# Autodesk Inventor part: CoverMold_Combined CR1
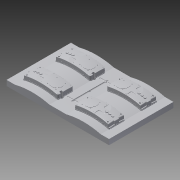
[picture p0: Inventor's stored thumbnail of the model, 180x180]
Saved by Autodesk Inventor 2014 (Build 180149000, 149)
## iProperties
Created: 2009-12
Part Number: CoverMold_Combined CR1
Document SubType Name: Modeling
Designer: gaom
Density: 1 g/cm^3
Material: Generic
Appearance: Default
Author: gaom
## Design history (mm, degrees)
node "CoverMold_AsmContainer" dims "d0" = 10
sketch "Sketch1"
  geometry: L1 (-350, 220)-(350, 220) reference; L2 (350, 220)-(350, -220) reference; L3 (350, -220)-(-350, -220) reference; L4 (-350, -220)-(-350, 220) reference; L5 (-350, 220)-(350, 220) reference; L6 (350, 220)-(350, -220) reference; L7 (350, -220)-(-350, -220) reference; L8 (-350, -220)-(-350, 220) reference; L9 (-350, 220)-(350, 220) reference; L10 (350, 220)-(350, -220) reference; L11 (350, -220)-(-350, -220) reference; L12 (-350, -220)-(-350, 220) reference; L13 (-350, 220)-(350, 220) reference; L14 (350, 220)-(350, -220) reference; L15 (350, -220)-(-350, -220) reference; L16 (-350, -220)-(-350, 220) reference; L17 (350, 220)-(-350, 220); L18 (-350, 220)-(-350, -220); L19 (-350, -220)-(350, -220); L20 (350, -220)-(350, 220)
  constraints: 8 end point, 2 parallel, 1 horizontal, 1 perpendicular
sketch "Sketch2"
  geometry: L1 (700, 0)-(0, 0) reference; L2 (0, 0)-(0, -440) reference; L3 (0, -440)-(700, -440) reference; L4 (700, -440)-(700, 0) reference
sketch "Sketch3"
  geometry: L1 (700, 0)-(0, 0) reference; L2 (0, 0)-(0, -440) reference; L3 (0, -440)-(700, -440) reference; L4 (700, -440)-(700, 0) reference
sketch "Sketch4"
  geometry: L1 (700, 0)-(0, 0) reference; L2 (0, 0)-(0, -440) reference; L3 (0, -440)-(700, -440) reference; L4 (700, -440)-(700, 0) reference
sketch "Sketch5"
  geometry: L1 (700, 0)-(0, 0) reference; L2 (0, 0)-(0, -440) reference; L3 (0, -440)-(700, -440) reference; L4 (700, -440)-(700, 0) reference
feature "Sculpt1"
body "Solid1"
node "CoverMold_cover_CR_1:1" dims "d0" = 10
node "CoverMold_cover_CR_2:1" dims "d0" = 10
node "CoverMold_cover_CR_3:1" dims "d0" = 10
node "CoverMold_cover_CR_4:1" dims "d0" = 10
feature "Surface1"
body "Srf1"
